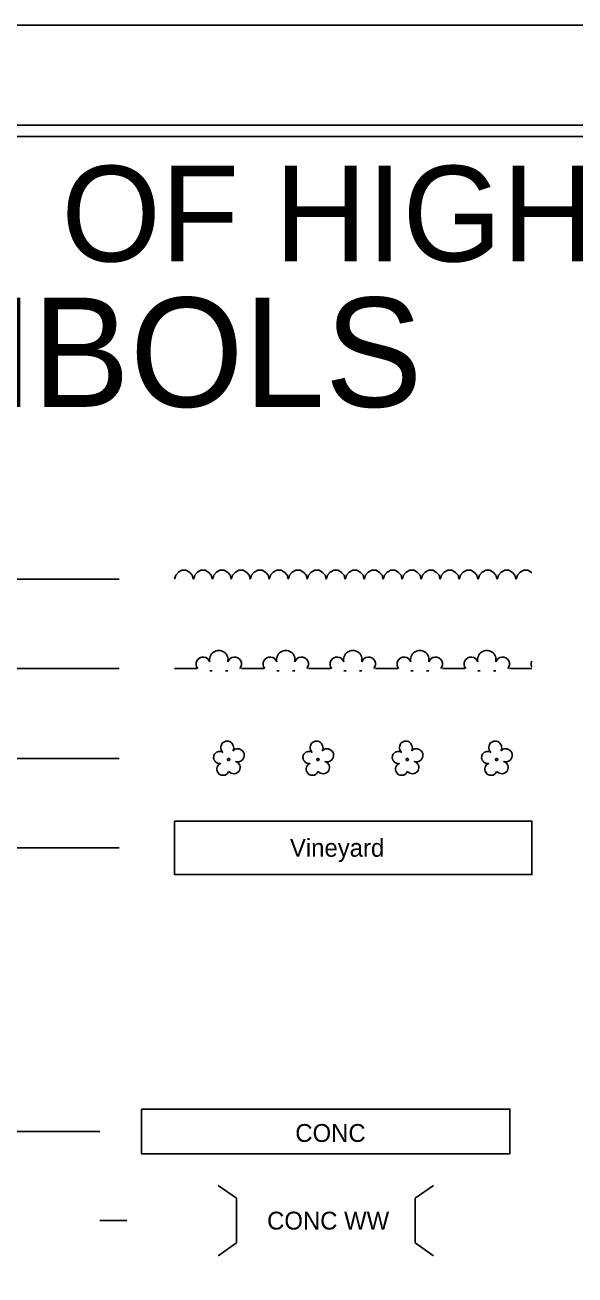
# Model space of a CAD drawing. Extents: x 1729989.5 to 1730023.2, y 539942.1 to 539964.1.
# Drawn here: x 1730012.8 to 1730015.26, y 539958.5 to 539964.1 of the extents above; entities that cross this region are included whole.
import ezdxf

# ---------------------------------------------------------------- set-up
doc = ezdxf.new("R2010")
doc.units = 0
for name, color, linetype in [('Sheet Cutting Line CELL', 7, 'Continuous'), ('Sheet Plot Border Inside CELL', 7, 'Continuous'), ('Sheet Plot Border Outside CELL', 7, 'Continuous'), ('Sheet Symbology CELL', 7, 'Continuous')]:
    doc.layers.add(name, color=color, linetype=linetype)

msp = doc.modelspace()

# ---------------------------------------------------------------- linework, layer by layer
at = {"layer": 'Sheet Cutting Line CELL'}
msp.add_line((1730023.2105, 539964.0971), (1729989.5305, 539964.0971), dxfattribs=at)
at = {"layer": 'Sheet Plot Border Inside CELL'}
msp.add_lwpolyline([(1729989.7905, 539942.5461), (1730023.1205, 539942.5461), (1730023.1205, 539963.6481), (1729989.7905, 539963.6481)], close=True, dxfattribs=at)
at = {"layer": 'Sheet Plot Border Outside CELL'}
msp.add_lwpolyline([(1729989.5305, 539942.0971), (1730023.2105, 539942.0971), (1730023.2105, 539964.0971), (1729989.5305, 539964.0971)], close=True, dxfattribs=at)
at = {"layer": 'Sheet Symbology CELL'}
for p, q in [((1730013.482, 539961.6461), (1730013.498, 539961.6551)), ((1730013.498, 539961.6551), (1730013.517, 539961.6551)), ((1730013.517, 539961.6551), (1730013.533, 539961.6451)), ((1730013.567, 539961.6461), (1730013.583, 539961.6551)), ((1730013.583, 539961.6551), (1730013.602, 539961.6551)), ((1730013.602, 539961.6551), (1730013.618, 539961.6451)), ((1730013.652, 539961.6461), (1730013.668, 539961.6551)), ((1730013.668, 539961.6551), (1730013.687, 539961.6551)), ((1730013.687, 539961.6551), (1730013.703, 539961.6451)), ((1730013.737, 539961.6461), (1730013.753, 539961.6551)), ((1730013.753, 539961.6551), (1730013.772, 539961.6551)), ((1730013.772, 539961.6551), (1730013.788, 539961.6451)), ((1730013.822, 539961.6461), (1730013.838, 539961.6551)), ((1730013.838, 539961.6551), (1730013.857, 539961.6551)), ((1730013.857, 539961.6551), (1730013.873, 539961.6451)), ((1730013.907, 539961.6461), (1730013.923, 539961.6551)), ((1730013.923, 539961.6551), (1730013.942, 539961.6551)), ((1730013.942, 539961.6551), (1730013.958, 539961.6451)), ((1730013.992, 539961.6461), (1730014.008, 539961.6551)), ((1730014.008, 539961.6551), (1730014.027, 539961.6551)), ((1730014.027, 539961.6551), (1730014.043, 539961.6451)), ((1730014.077, 539961.6461), (1730014.093, 539961.6551)), ((1730014.093, 539961.6551), (1730014.112, 539961.6551)), ((1730014.112, 539961.6551), (1730014.128, 539961.6451)), ((1730014.162, 539961.6461), (1730014.178, 539961.6551)), ((1730014.178, 539961.6551), (1730014.197, 539961.6551)), ((1730014.197, 539961.6551), (1730014.213, 539961.6451)), ((1730014.247, 539961.6461), (1730014.263, 539961.6551)), ((1730014.263, 539961.6551), (1730014.282, 539961.6551)), ((1730014.282, 539961.6551), (1730014.298, 539961.6451)), ((1730014.332, 539961.6461), (1730014.348, 539961.6551)), ((1730014.348, 539961.6551), (1730014.367, 539961.6551)), ((1730014.367, 539961.6551), (1730014.383, 539961.6451)), ((1730014.417, 539961.6461), (1730014.433, 539961.6551)), ((1730014.433, 539961.6551), (1730014.452, 539961.6551)), ((1730014.452, 539961.6551), (1730014.468, 539961.6451)), ((1730014.502, 539961.6461), (1730014.518, 539961.6551)), ((1730014.518, 539961.6551), (1730014.537, 539961.6551)), ((1730014.537, 539961.6551), (1730014.553, 539961.6451)), ((1730014.587, 539961.6461), (1730014.603, 539961.6551)), ((1730014.603, 539961.6551), (1730014.622, 539961.6551)), ((1730014.622, 539961.6551), (1730014.638, 539961.6451)), ((1730014.672, 539961.6461), (1730014.688, 539961.6551)), ((1730014.688, 539961.6551), (1730014.707, 539961.6551)), ((1730014.707, 539961.6551), (1730014.723, 539961.6451)), ((1730014.757, 539961.6461), (1730014.773, 539961.6551)), ((1730014.773, 539961.6551), (1730014.792, 539961.6551)), ((1730014.792, 539961.6551), (1730014.808, 539961.6451)), ((1730014.842, 539961.6461), (1730014.858, 539961.6551)), ((1730014.858, 539961.6551), (1730014.877, 539961.6551)), ((1730014.877, 539961.6551), (1730014.893, 539961.6451)), ((1730014.927, 539961.6461), (1730014.943, 539961.6551)), ((1730014.943, 539961.6551), (1730014.962, 539961.6551)), ((1730014.962, 539961.6551), (1730014.978, 539961.6451)), ((1730015.012, 539961.6461), (1730015.028, 539961.6551)), ((1730015.028, 539961.6551), (1730015.047, 539961.6551)), ((1730015.047, 539961.6551), (1730015.063, 539961.6451)), ((1730013.2161, 539961.6141), (1730008.9624, 539961.6141)), ((1730013.464, 539961.6141), (1730013.47, 539961.6331)), ((1730013.47, 539961.6331), (1730013.482, 539961.6461)), ((1730013.533, 539961.6451), (1730013.544, 539961.6321)), ((1730013.544, 539961.6321), (1730013.548, 539961.6151)), ((1730013.549, 539961.6141), (1730013.555, 539961.6331)), ((1730013.555, 539961.6331), (1730013.567, 539961.6461)), ((1730013.618, 539961.6451), (1730013.629, 539961.6321)), ((1730013.629, 539961.6321), (1730013.633, 539961.6151)), ((1730013.634, 539961.6141), (1730013.64, 539961.6331)), ((1730013.64, 539961.6331), (1730013.652, 539961.6461)), ((1730013.703, 539961.6451), (1730013.714, 539961.6321)), ((1730013.714, 539961.6321), (1730013.718, 539961.6151)), ((1730013.719, 539961.6141), (1730013.725, 539961.6331)), ((1730013.725, 539961.6331), (1730013.737, 539961.6461)), ((1730013.788, 539961.6451), (1730013.799, 539961.6321)), ((1730013.799, 539961.6321), (1730013.803, 539961.6151)), ((1730013.804, 539961.6141), (1730013.81, 539961.6331)), ((1730013.81, 539961.6331), (1730013.822, 539961.6461)), ((1730013.873, 539961.6451), (1730013.884, 539961.6321)), ((1730013.884, 539961.6321), (1730013.888, 539961.6151)), ((1730013.889, 539961.6141), (1730013.895, 539961.6331)), ((1730013.895, 539961.6331), (1730013.907, 539961.6461)), ((1730013.958, 539961.6451), (1730013.969, 539961.6321)), ((1730013.969, 539961.6321), (1730013.973, 539961.6151)), ((1730013.974, 539961.6141), (1730013.98, 539961.6331)), ((1730013.98, 539961.6331), (1730013.992, 539961.6461)), ((1730014.043, 539961.6451), (1730014.054, 539961.6321)), ((1730014.054, 539961.6321), (1730014.058, 539961.6151)), ((1730014.059, 539961.6141), (1730014.065, 539961.6331)), ((1730014.065, 539961.6331), (1730014.077, 539961.6461)), ((1730014.128, 539961.6451), (1730014.139, 539961.6321)), ((1730014.139, 539961.6321), (1730014.143, 539961.6151)), ((1730014.144, 539961.6141), (1730014.15, 539961.6331)), ((1730014.15, 539961.6331), (1730014.162, 539961.6461)), ((1730014.213, 539961.6451), (1730014.224, 539961.6321)), ((1730014.224, 539961.6321), (1730014.228, 539961.6151)), ((1730014.229, 539961.6141), (1730014.235, 539961.6331)), ((1730014.235, 539961.6331), (1730014.247, 539961.6461)), ((1730014.298, 539961.6451), (1730014.309, 539961.6321)), ((1730014.309, 539961.6321), (1730014.313, 539961.6151)), ((1730014.314, 539961.6141), (1730014.32, 539961.6331)), ((1730014.32, 539961.6331), (1730014.332, 539961.6461)), ((1730014.383, 539961.6451), (1730014.394, 539961.6321)), ((1730014.394, 539961.6321), (1730014.398, 539961.6151)), ((1730014.399, 539961.6141), (1730014.405, 539961.6331)), ((1730014.405, 539961.6331), (1730014.417, 539961.6461)), ((1730014.468, 539961.6451), (1730014.479, 539961.6321)), ((1730014.479, 539961.6321), (1730014.483, 539961.6151)), ((1730014.484, 539961.6141), (1730014.49, 539961.6331)), ((1730014.49, 539961.6331), (1730014.502, 539961.6461)), ((1730014.553, 539961.6451), (1730014.564, 539961.6321)), ((1730014.564, 539961.6321), (1730014.568, 539961.6151)), ((1730014.569, 539961.6141), (1730014.575, 539961.6331)), ((1730014.575, 539961.6331), (1730014.587, 539961.6461)), ((1730014.638, 539961.6451), (1730014.649, 539961.6321)), ((1730014.649, 539961.6321), (1730014.653, 539961.6151)), ((1730014.654, 539961.6141), (1730014.66, 539961.6331)), ((1730014.66, 539961.6331), (1730014.672, 539961.6461)), ((1730014.723, 539961.6451), (1730014.734, 539961.6321)), ((1730014.734, 539961.6321), (1730014.738, 539961.6151)), ((1730014.739, 539961.6141), (1730014.745, 539961.6331)), ((1730014.745, 539961.6331), (1730014.757, 539961.6461)), ((1730014.808, 539961.6451), (1730014.819, 539961.6321)), ((1730014.819, 539961.6321), (1730014.823, 539961.6151)), ((1730014.824, 539961.6141), (1730014.83, 539961.6331)), ((1730014.83, 539961.6331), (1730014.842, 539961.6461)), ((1730014.893, 539961.6451), (1730014.904, 539961.6321)), ((1730014.904, 539961.6321), (1730014.908, 539961.6151)), ((1730014.909, 539961.6141), (1730014.915, 539961.6331)), ((1730014.915, 539961.6331), (1730014.927, 539961.6461)), ((1730014.978, 539961.6451), (1730014.989, 539961.6321)), ((1730014.989, 539961.6321), (1730014.993, 539961.6151)), ((1730014.994, 539961.6141), (1730015, 539961.6331)), ((1730015, 539961.6331), (1730015.012, 539961.6461)), ((1730015.063, 539961.6451), (1730015.064, 539961.6441)), ((1730013.2161, 539961.2141), (1730009.5936, 539961.2141)), ((1730013.464, 539961.2141), (1730013.564, 539961.2141)), ((1730013.623, 539961.2041), (1730013.633, 539961.2041)), ((1730013.693, 539961.2041), (1730013.703, 539961.2041)), ((1730013.764, 539961.2141), (1730013.864, 539961.2141)), ((1730013.923, 539961.2041), (1730013.933, 539961.2041)), ((1730013.993, 539961.2041), (1730014.003, 539961.2041)), ((1730014.064, 539961.2141), (1730014.164, 539961.2141)), ((1730014.223, 539961.2041), (1730014.233, 539961.2041)), ((1730014.293, 539961.2041), (1730014.303, 539961.2041)), ((1730014.364, 539961.2141), (1730014.464, 539961.2141)), ((1730014.523, 539961.2041), (1730014.533, 539961.2041)), ((1730014.593, 539961.2041), (1730014.603, 539961.2041)), ((1730014.664, 539961.2141), (1730014.764, 539961.2141)), ((1730014.823, 539961.2041), (1730014.833, 539961.2041)), ((1730014.893, 539961.2041), (1730014.903, 539961.2041)), ((1730014.964, 539961.2141), (1730015.064, 539961.2141)), ((1730013.2171, 539960.8114), (1730009.1184, 539960.8114)), ((1730013.2171, 539960.4114), (1730009.1184, 539960.4114)), ((1730013.1308, 539959.1413), (1730011.4423, 539959.1413)), ((1730013.6598, 539958.8985), (1730013.7418, 539958.8413)), ((1730014.6238, 539958.8985), (1730014.5418, 539958.8413)), ((1730013.7418, 539958.8413), (1730013.7418, 539958.6413)), ((1730014.5418, 539958.8413), (1730014.5418, 539958.6413)), ((1730013.1308, 539958.7413), (1730013.2505, 539958.7413)), ((1730013.6598, 539958.584), (1730013.7418, 539958.6413)), ((1730014.6238, 539958.584), (1730014.5418, 539958.6413))]:
    msp.add_line(p, q, dxfattribs=at)
msp.add_lwpolyline([(1730022.8705, 539963.5971), (1729992.8705, 539963.5971), (1729992.8705, 539942.6174), (1730022.8705, 539942.6174)], close=True, dxfattribs=at)
for points in [[(1730013.726, 539960.8464), (1730013.729, 539960.8524), (1730013.73, 539960.8584), (1730013.729, 539960.8644), (1730013.728, 539960.8704), (1730013.725, 539960.8754), (1730013.722, 539960.8804), (1730013.717, 539960.8844), (1730013.712, 539960.8874), (1730013.705, 539960.8894), (1730013.7, 539960.8894), (1730013.694, 539960.8884), (1730013.688, 539960.8864), (1730013.683, 539960.8834), (1730013.678, 539960.8794), (1730013.675, 539960.8734), (1730013.673, 539960.8684), (1730013.672, 539960.8624), (1730013.672, 539960.8564), (1730013.673, 539960.8504), (1730013.676, 539960.8454), (1730013.68, 539960.8394), (1730013.675, 539960.8424), (1730013.669, 539960.8434), (1730013.663, 539960.8434), (1730013.658, 539960.8414), (1730013.653, 539960.8394), (1730013.648, 539960.8354), (1730013.644, 539960.8314), (1730013.641, 539960.8264), (1730013.64, 539960.8214), (1730013.639, 539960.8144), (1730013.64, 539960.8094), (1730013.642, 539960.8044), (1730013.646, 539960.7994), (1730013.649, 539960.7954), (1730013.654, 539960.7924), (1730013.66, 539960.7894), (1730013.665, 539960.7884), (1730013.671, 539960.7884), (1730013.666, 539960.7864), (1730013.661, 539960.7824), (1730013.658, 539960.7784), (1730013.656, 539960.7724), (1730013.654, 539960.7664), (1730013.654, 539960.7614), (1730013.655, 539960.7554), (1730013.658, 539960.7504), (1730013.661, 539960.7454), (1730013.665, 539960.7414), (1730013.67, 539960.7384), (1730013.675, 539960.7364), (1730013.681, 539960.7364), (1730013.687, 539960.7364), (1730013.692, 539960.7374), (1730013.697, 539960.7414), (1730013.702, 539960.7444), (1730013.707, 539960.7534)], [(1730014.126, 539960.8464), (1730014.129, 539960.8524), (1730014.13, 539960.8584), (1730014.129, 539960.8644), (1730014.128, 539960.8704), (1730014.125, 539960.8754), (1730014.122, 539960.8804), (1730014.117, 539960.8844), (1730014.112, 539960.8874), (1730014.105, 539960.8894), (1730014.1, 539960.8894), (1730014.094, 539960.8884), (1730014.088, 539960.8864), (1730014.083, 539960.8834), (1730014.078, 539960.8794), (1730014.075, 539960.8734), (1730014.073, 539960.8684), (1730014.072, 539960.8624), (1730014.072, 539960.8564), (1730014.073, 539960.8504), (1730014.076, 539960.8454), (1730014.08, 539960.8394), (1730014.075, 539960.8424), (1730014.069, 539960.8434), (1730014.063, 539960.8434), (1730014.058, 539960.8414), (1730014.053, 539960.8394), (1730014.048, 539960.8354), (1730014.044, 539960.8314), (1730014.041, 539960.8264), (1730014.04, 539960.8214), (1730014.039, 539960.8144), (1730014.04, 539960.8094), (1730014.042, 539960.8044), (1730014.046, 539960.7994), (1730014.049, 539960.7954), (1730014.054, 539960.7924), (1730014.06, 539960.7894), (1730014.065, 539960.7884), (1730014.071, 539960.7884), (1730014.066, 539960.7864), (1730014.061, 539960.7824), (1730014.058, 539960.7784), (1730014.056, 539960.7724), (1730014.054, 539960.7664), (1730014.054, 539960.7614), (1730014.055, 539960.7554), (1730014.058, 539960.7504), (1730014.061, 539960.7454), (1730014.065, 539960.7414), (1730014.07, 539960.7384), (1730014.075, 539960.7364), (1730014.081, 539960.7364), (1730014.087, 539960.7364), (1730014.092, 539960.7374), (1730014.097, 539960.7414), (1730014.102, 539960.7444), (1730014.107, 539960.7534)], [(1730014.526, 539960.8464), (1730014.529, 539960.8524), (1730014.53, 539960.8584), (1730014.529, 539960.8644), (1730014.528, 539960.8704), (1730014.525, 539960.8754), (1730014.522, 539960.8804), (1730014.517, 539960.8844), (1730014.512, 539960.8874), (1730014.505, 539960.8894), (1730014.5, 539960.8894), (1730014.494, 539960.8884), (1730014.488, 539960.8864), (1730014.483, 539960.8834), (1730014.478, 539960.8794), (1730014.475, 539960.8734), (1730014.473, 539960.8684), (1730014.472, 539960.8624), (1730014.472, 539960.8564), (1730014.473, 539960.8504), (1730014.476, 539960.8454), (1730014.48, 539960.8394), (1730014.475, 539960.8424), (1730014.469, 539960.8434), (1730014.463, 539960.8434), (1730014.458, 539960.8414), (1730014.453, 539960.8394), (1730014.448, 539960.8354), (1730014.444, 539960.8314), (1730014.441, 539960.8264), (1730014.44, 539960.8214), (1730014.439, 539960.8144), (1730014.44, 539960.8094), (1730014.442, 539960.8044), (1730014.446, 539960.7994), (1730014.449, 539960.7954), (1730014.454, 539960.7924), (1730014.46, 539960.7894), (1730014.465, 539960.7884), (1730014.471, 539960.7884), (1730014.466, 539960.7864), (1730014.461, 539960.7824), (1730014.458, 539960.7784), (1730014.456, 539960.7724), (1730014.454, 539960.7664), (1730014.454, 539960.7614), (1730014.455, 539960.7554), (1730014.458, 539960.7504), (1730014.461, 539960.7454), (1730014.465, 539960.7414), (1730014.47, 539960.7384), (1730014.475, 539960.7364), (1730014.481, 539960.7364), (1730014.487, 539960.7364), (1730014.492, 539960.7374), (1730014.497, 539960.7414), (1730014.502, 539960.7444), (1730014.507, 539960.7534)], [(1730014.926, 539960.8464), (1730014.929, 539960.8524), (1730014.93, 539960.8584), (1730014.929, 539960.8644), (1730014.928, 539960.8704), (1730014.925, 539960.8754), (1730014.922, 539960.8804), (1730014.917, 539960.8844), (1730014.912, 539960.8874), (1730014.905, 539960.8894), (1730014.9, 539960.8894), (1730014.894, 539960.8884), (1730014.888, 539960.8864), (1730014.883, 539960.8834), (1730014.878, 539960.8794), (1730014.875, 539960.8734), (1730014.873, 539960.8684), (1730014.872, 539960.8624), (1730014.872, 539960.8564), (1730014.873, 539960.8504), (1730014.876, 539960.8454), (1730014.88, 539960.8394), (1730014.875, 539960.8424), (1730014.869, 539960.8434), (1730014.863, 539960.8434), (1730014.858, 539960.8414), (1730014.853, 539960.8394), (1730014.848, 539960.8354), (1730014.844, 539960.8314), (1730014.841, 539960.8264), (1730014.84, 539960.8214), (1730014.839, 539960.8144), (1730014.84, 539960.8094), (1730014.842, 539960.8044), (1730014.846, 539960.7994), (1730014.849, 539960.7954), (1730014.854, 539960.7924), (1730014.86, 539960.7894), (1730014.865, 539960.7884), (1730014.871, 539960.7884), (1730014.866, 539960.7864), (1730014.861, 539960.7824), (1730014.858, 539960.7784), (1730014.856, 539960.7724), (1730014.854, 539960.7664), (1730014.854, 539960.7614), (1730014.855, 539960.7554), (1730014.858, 539960.7504), (1730014.861, 539960.7454), (1730014.865, 539960.7414), (1730014.87, 539960.7384), (1730014.875, 539960.7364), (1730014.881, 539960.7364), (1730014.887, 539960.7364), (1730014.892, 539960.7374), (1730014.897, 539960.7414), (1730014.902, 539960.7444), (1730014.907, 539960.7534)], [(1730013.709, 539960.8114), (1730013.706, 539960.8114), (1730013.704, 539960.8104), (1730013.702, 539960.8094), (1730013.702, 539960.8064), (1730013.702, 539960.8044), (1730013.704, 539960.8024), (1730013.707, 539960.8024), (1730013.709, 539960.8024), (1730013.711, 539960.8044), (1730013.712, 539960.8074), (1730013.711, 539960.8094), (1730013.709, 539960.8114)], [(1730013.707, 539960.7534), (1730013.719, 539960.7464), (1730013.725, 539960.7444), (1730013.731, 539960.7434), (1730013.737, 539960.7444), (1730013.742, 539960.7464), (1730013.747, 539960.7494), (1730013.752, 539960.7534), (1730013.755, 539960.7584), (1730013.757, 539960.7634), (1730013.759, 539960.7694), (1730013.758, 539960.7754), (1730013.757, 539960.7814), (1730013.753, 539960.7874), (1730013.75, 539960.7914), (1730013.745, 539960.7944), (1730013.739, 539960.7974), (1730013.745, 539960.7964), (1730013.752, 539960.7964), (1730013.757, 539960.7984), (1730013.763, 539960.8014), (1730013.768, 539960.8044), (1730013.772, 539960.8094), (1730013.775, 539960.8154), (1730013.776, 539960.8214), (1730013.777, 539960.8274), (1730013.776, 539960.8334), (1730013.774, 539960.8394), (1730013.77, 539960.8444), (1730013.765, 539960.8494), (1730013.76, 539960.8524), (1730013.754, 539960.8544), (1730013.748, 539960.8554), (1730013.742, 539960.8554), (1730013.736, 539960.8534), (1730013.731, 539960.8504), (1730013.726, 539960.8464)], [(1730014.109, 539960.8114), (1730014.106, 539960.8114), (1730014.104, 539960.8104), (1730014.102, 539960.8094), (1730014.102, 539960.8064), (1730014.102, 539960.8044), (1730014.104, 539960.8024), (1730014.107, 539960.8024), (1730014.109, 539960.8024), (1730014.111, 539960.8044), (1730014.112, 539960.8074), (1730014.111, 539960.8094), (1730014.109, 539960.8114)], [(1730014.107, 539960.7534), (1730014.119, 539960.7464), (1730014.125, 539960.7444), (1730014.131, 539960.7434), (1730014.137, 539960.7444), (1730014.142, 539960.7464), (1730014.147, 539960.7494), (1730014.152, 539960.7534), (1730014.155, 539960.7584), (1730014.157, 539960.7634), (1730014.159, 539960.7694), (1730014.158, 539960.7754), (1730014.157, 539960.7814), (1730014.153, 539960.7874), (1730014.15, 539960.7914), (1730014.145, 539960.7944), (1730014.139, 539960.7974), (1730014.145, 539960.7964), (1730014.152, 539960.7964), (1730014.157, 539960.7984), (1730014.163, 539960.8014), (1730014.168, 539960.8044), (1730014.172, 539960.8094), (1730014.175, 539960.8154), (1730014.176, 539960.8214), (1730014.177, 539960.8274), (1730014.176, 539960.8334), (1730014.174, 539960.8394), (1730014.17, 539960.8444), (1730014.165, 539960.8494), (1730014.16, 539960.8524), (1730014.154, 539960.8544), (1730014.148, 539960.8554), (1730014.142, 539960.8554), (1730014.136, 539960.8534), (1730014.131, 539960.8504), (1730014.126, 539960.8464)], [(1730014.509, 539960.8114), (1730014.506, 539960.8114), (1730014.504, 539960.8104), (1730014.502, 539960.8094), (1730014.502, 539960.8064), (1730014.502, 539960.8044), (1730014.504, 539960.8024), (1730014.507, 539960.8024), (1730014.509, 539960.8024), (1730014.511, 539960.8044), (1730014.512, 539960.8074), (1730014.511, 539960.8094), (1730014.509, 539960.8114)], [(1730014.507, 539960.7534), (1730014.519, 539960.7464), (1730014.525, 539960.7444), (1730014.531, 539960.7434), (1730014.537, 539960.7444), (1730014.542, 539960.7464), (1730014.547, 539960.7494), (1730014.552, 539960.7534), (1730014.555, 539960.7584), (1730014.557, 539960.7634), (1730014.559, 539960.7694), (1730014.558, 539960.7754), (1730014.557, 539960.7814), (1730014.553, 539960.7874), (1730014.55, 539960.7914), (1730014.545, 539960.7944), (1730014.539, 539960.7974), (1730014.545, 539960.7964), (1730014.552, 539960.7964), (1730014.557, 539960.7984), (1730014.563, 539960.8014), (1730014.568, 539960.8044), (1730014.572, 539960.8094), (1730014.575, 539960.8154), (1730014.576, 539960.8214), (1730014.577, 539960.8274), (1730014.576, 539960.8334), (1730014.574, 539960.8394), (1730014.57, 539960.8444), (1730014.565, 539960.8494), (1730014.56, 539960.8524), (1730014.554, 539960.8544), (1730014.548, 539960.8554), (1730014.542, 539960.8554), (1730014.536, 539960.8534), (1730014.531, 539960.8504), (1730014.526, 539960.8464)], [(1730014.909, 539960.8114), (1730014.906, 539960.8114), (1730014.904, 539960.8104), (1730014.902, 539960.8094), (1730014.902, 539960.8064), (1730014.902, 539960.8044), (1730014.904, 539960.8024), (1730014.907, 539960.8024), (1730014.909, 539960.8024), (1730014.911, 539960.8044), (1730014.912, 539960.8074), (1730014.911, 539960.8094), (1730014.909, 539960.8114)], [(1730014.907, 539960.7534), (1730014.919, 539960.7464), (1730014.925, 539960.7444), (1730014.931, 539960.7434), (1730014.937, 539960.7444), (1730014.942, 539960.7464), (1730014.947, 539960.7494), (1730014.952, 539960.7534), (1730014.955, 539960.7584), (1730014.957, 539960.7634), (1730014.959, 539960.7694), (1730014.958, 539960.7754), (1730014.957, 539960.7814), (1730014.953, 539960.7874), (1730014.95, 539960.7914), (1730014.945, 539960.7944), (1730014.939, 539960.7974), (1730014.945, 539960.7964), (1730014.952, 539960.7964), (1730014.957, 539960.7984), (1730014.963, 539960.8014), (1730014.968, 539960.8044), (1730014.972, 539960.8094), (1730014.975, 539960.8154), (1730014.976, 539960.8214), (1730014.977, 539960.8274), (1730014.976, 539960.8334), (1730014.974, 539960.8394), (1730014.97, 539960.8444), (1730014.965, 539960.8494), (1730014.96, 539960.8524), (1730014.954, 539960.8544), (1730014.948, 539960.8554), (1730014.942, 539960.8554), (1730014.936, 539960.8534), (1730014.931, 539960.8504), (1730014.926, 539960.8464)], [(1730013.465, 539960.5314), (1730015.065, 539960.5314), (1730015.065, 539960.2914), (1730013.465, 539960.2914), (1730013.465, 539960.5314)], [(1730013.3168, 539959.2413), (1730014.9668, 539959.2413), (1730014.9668, 539959.0413), (1730013.3168, 539959.0413), (1730013.3168, 539959.2413)]]:
    msp.add_lwpolyline(points, dxfattribs=at)
for centre, radius, start, end in [((1730013.593, 539961.2344), 0.0316, 18.435, 219.2315), ((1730013.663, 539961.2544), 0.0412, 345.9638, 194.0362), ((1730013.733, 539961.2344), 0.0316, 320.7685, 161.5651), ((1730013.8929, 539961.2344), 0.0316, 18.435, 219.2315), ((1730013.9629, 539961.2544), 0.0412, 345.9638, 194.0362), ((1730014.0329, 539961.2344), 0.0316, 320.7685, 161.5651), ((1730014.1929, 539961.2344), 0.0316, 18.435, 219.2315), ((1730014.2629, 539961.2544), 0.0412, 345.9638, 194.0362), ((1730014.3329, 539961.2344), 0.0316, 320.7685, 161.5651), ((1730014.4929, 539961.2344), 0.0316, 18.435, 219.2315), ((1730014.5629, 539961.2544), 0.0412, 345.9638, 194.0362), ((1730014.6329, 539961.2344), 0.0316, 320.7685, 161.5651), ((1730014.7929, 539961.2344), 0.0316, 18.435, 219.2315), ((1730014.8629, 539961.2544), 0.0412, 345.9638, 194.0362), ((1730014.9329, 539961.2344), 0.0316, 320.7685, 161.5651), ((1730015.0929, 539961.2344), 0.0316, 156.251, 203.749)]:
    msp.add_arc(centre, radius, start, end, dxfattribs=at)

# ---------------------------------------------------------------- texts
for s, height, p in [('STATE OF NORTH CAROLINA, DIVISION OF HIGHWAYS', 0.42838, (1730001.8818, 539963.0379)), ('CONVENTIONAL  PLAN SHEET SYMBOLS', 0.489606, (1730001.6227, 539962.3865)), ('CONC', 0.08, (1730014.0055, 539959.094))]:
    msp.add_text(s, height=height, dxfattribs=at).set_placement(p)
for s, p in [('Vineyard', (1730013.9815, 539960.3714)), ('CONC WW', (1730013.8793, 539958.7013))]:
    msp.add_text(s, height=0.08, rotation=0, dxfattribs=at).set_placement(p)

doc.saveas('drawing.dxf')
